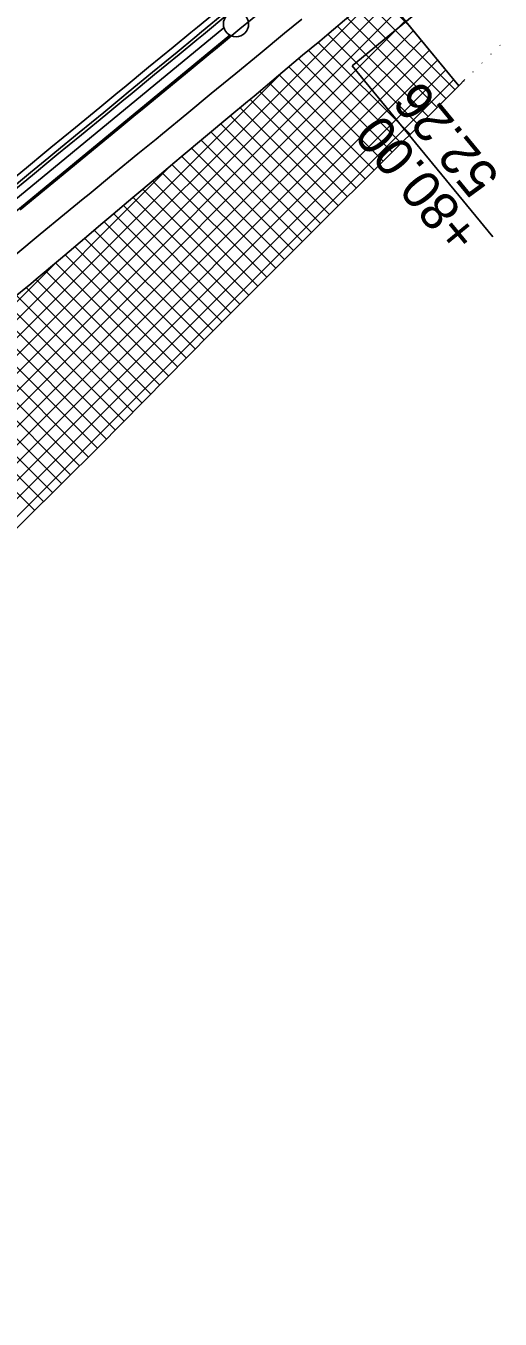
# Model space of a CAD drawing. Extents: x 1147550 to 1149124, y 2017436 to 2018779.
# Drawn here: x 1149049.5 to 1149124.5, y 2018399.2 to 2018603.7 of the extents above; entities that cross this region are included whole.
import ezdxf

# ---------------------------------------------------------------- set-up
doc = ezdxf.new("R2010")
doc.units = 0
for name, color, linetype in [('S_ELECTRIC_UTILITIES', 7, 'Continuous'), ('S_HEADWALL', 7, 'Continuous'), ('S_IRON_PIN_ANNOT', 7, 'Continuous'), ('S_MAILBOX', 7, 'Continuous'), ('S_SECONDARY_CTL', 7, 'Continuous'), ('S_TELEPHONE_UTILITIES', 7, 'Continuous'), ('S_TELEPHONE_UTILITIES_ANNOT', 7, 'Continuous')]:
    doc.layers.add(name, color=color, linetype=linetype)

msp = doc.modelspace()

# ---------------------------------------------------------------- linework, layer by layer
at = {"layer": 'S_ELECTRIC_UTILITIES'}
msp.add_lwpolyline([(1149101.12, 2018597.36), (1149123.36, 2018570.33)], dxfattribs=at)
at = {"layer": 'S_HEADWALL'}
msp.add_line((1149117.99, 2018594.17), (1149102.78, 2018612.66), dxfattribs=at)
at = {"layer": 'S_IRON_PIN_ANNOT'}
for p, q in [((1148922.38, 2018425.84), (1149105.68, 2018609.13)), ((1149104.93, 2018608.83), (1149110.52, 2018603.24)), ((1148923.66, 2018424.29), (1149106.95, 2018607.58)), ((1149101.87, 2018606.24), (1149115.95, 2018592.16)), ((1149103.4, 2018607.54), (1149117.37, 2018593.57)), ((1148924.94, 2018422.74), (1149108.23, 2018606.03)), ((1148926.21, 2018421.18), (1149109.51, 2018604.48)), ((1149100.34, 2018604.95), (1149114.52, 2018590.76)), ((1148927.49, 2018419.63), (1149110.78, 2018602.93)), ((1149097.27, 2018602.35), (1149111.69, 2018587.94)), ((1149098.8, 2018603.65), (1149113.1, 2018589.35)), ((1148928.77, 2018418.08), (1149112.06, 2018601.38)), ((1149095.74, 2018601.06), (1149110.27, 2018586.53)), ((1149124.46, 2018600.62), (1149124.49, 2018600.59)), ((1148931, 2018417.49), (1149113.34, 2018599.82)), ((1148944.72, 2018428.38), (1149114.61, 2018598.27)), ((1149092.65, 2018598.49), (1149107.43, 2018583.71)), ((1149094.19, 2018599.77), (1149108.85, 2018585.12)), ((1149123.04, 2018599.21), (1149123.07, 2018599.18)), ((1148921.11, 2018427.39), (1149089.87, 2018596.15)), ((1148963.77, 2018444.6), (1149115.89, 2018596.72)), ((1149091.11, 2018597.2), (1149106.02, 2018582.29)), ((1149120.19, 2018596.41), (1149120.22, 2018596.38)), ((1149121.61, 2018597.81), (1149121.64, 2018597.78)), ((1148996.51, 2018474.51), (1149117.17, 2018595.17)), ((1149088.04, 2018594.62), (1149103.18, 2018579.47)), ((1149089.57, 2018595.91), (1149104.6, 2018580.88)), ((1149118.76, 2018595), (1149118.8, 2018594.97)), ((1149084.97, 2018592.03), (1149100.35, 2018576.65)), ((1149086.5, 2018593.32), (1149101.76, 2018578.06)), ((1149083.43, 2018590.74), (1149098.93, 2018575.24)), ((1149080.34, 2018588.17), (1149096.09, 2018572.42)), ((1149081.88, 2018589.46), (1149097.51, 2018573.83)), ((1149078.8, 2018586.89), (1149094.68, 2018571)), ((1149075.71, 2018584.32), (1149091.85, 2018568.18)), ((1149077.25, 2018585.6), (1149093.27, 2018569.59)), ((1148919.83, 2018428.94), (1149072.62, 2018581.74)), ((1149072.63, 2018581.74), (1149089.02, 2018565.35)), ((1149074.17, 2018583.03), (1149090.44, 2018566.76)), ((1149071.09, 2018580.45), (1149087.61, 2018563.93)), ((1149068.03, 2018577.86), (1149084.78, 2018561.1)), ((1149069.56, 2018579.15), (1149086.2, 2018562.52)), ((1149066.49, 2018576.56), (1149083.37, 2018559.69)), ((1149063.42, 2018573.97), (1149080.54, 2018556.86)), ((1149064.96, 2018575.27), (1149081.95, 2018558.28)), ((1149061.89, 2018572.68), (1149079.12, 2018555.45)), ((1149058.82, 2018570.09), (1149076.32, 2018552.6)), ((1149060.36, 2018571.39), (1149077.72, 2018554.02)), ((1149055.76, 2018567.5), (1149073.51, 2018549.75)), ((1149057.29, 2018568.8), (1149074.91, 2018551.17)), ((1148918.55, 2018430.5), (1149054.51, 2018566.45)), ((1149054.22, 2018566.21), (1149072.11, 2018548.32)), ((1149051.14, 2018563.63), (1149069.3, 2018545.47)), ((1149052.68, 2018564.92), (1149070.7, 2018546.9)), ((1149049.6, 2018562.34), (1149067.9, 2018544.05)), ((1149046.51, 2018559.78), (1149065.09, 2018541.2)), ((1149048.05, 2018561.06), (1149066.49, 2018542.62)), ((1149043.41, 2018557.22), (1149062.29, 2018538.34)), ((1149044.96, 2018558.5), (1149063.69, 2018539.77)), ((1149041.87, 2018555.93), (1149060.88, 2018536.92)), ((1149038.78, 2018553.36), (1149058.03, 2018534.11)), ((1149040.33, 2018554.65), (1149059.45, 2018535.52)), ((1149037.24, 2018552.08), (1149056.61, 2018532.71)), ((1149034.15, 2018549.51), (1149053.76, 2018529.9)), ((1149035.7, 2018550.79), (1149055.18, 2018531.31)), ((1149031.07, 2018546.93), (1149050.91, 2018527.1)), ((1149032.61, 2018548.22), (1149052.33, 2018528.5))]:
    msp.add_line(p, q, dxfattribs=at)
for points in [[(1149118.94, 2018595.18), (1149117.96, 2018594.21), (1149105.52, 2018609.33)], [(1149100.94, 2018605.45), (1149097.12, 2018602.22), (1149095.99, 2018601.27), (1149093.28, 2018599.02), (1149089.45, 2018595.8), (1149085.62, 2018592.58), (1149084.56, 2018591.69), (1149081.79, 2018589.38), (1149077.95, 2018586.18), (1149074.1, 2018582.98), (1149073.1, 2018582.14), (1149070.28, 2018579.76), (1149066.46, 2018576.53), (1149062.64, 2018573.31), (1149061.71, 2018572.52), (1149058.81, 2018570.08), (1149054.99, 2018566.86), (1149051.16, 2018563.64), (1149050.3, 2018562.92), (1149047.32, 2018560.45)], [(1148725.05, 2018295.78), (1148737.29, 2018302.31), (1148759.39, 2018313.93), (1148781.46, 2018325.68), (1148803.37, 2018337.66), (1148825.28, 2018349.66), (1148846.98, 2018361.91), (1148869.23, 2018375.5), (1148890.45, 2018388.71), (1148911.17, 2018402.69), (1148932.43, 2018418.55), (1148951.91, 2018434.12), (1148970.58, 2018450.61), (1148989.32, 2018467.79), (1149007.56, 2018484.84), (1149025.52, 2018502.19), (1149043.36, 2018519.65), (1149061.14, 2018537.18), (1149078.8, 2018555.13), (1149096.46, 2018572.78), (1149114.15, 2018590.39), (1149117.96, 2018594.21)]]:
    msp.add_lwpolyline(points, dxfattribs=at)
at = {"layer": 'S_MAILBOX'}
msp.add_lwpolyline([(1149101.12, 2018597.36), (1149116.55, 2018610.09)], dxfattribs=at)
at = {"layer": 'S_SECONDARY_CTL'}
msp.add_lwpolyline([(1149047.32, 2018560.45), (1149050.3, 2018562.92), (1149051.16, 2018563.64), (1149054.99, 2018566.86), (1149058.81, 2018570.08), (1149061.71, 2018572.52), (1149062.64, 2018573.31), (1149066.46, 2018576.53), (1149070.28, 2018579.76), (1149073.1, 2018582.14), (1149074.1, 2018582.98), (1149077.95, 2018586.18), (1149081.79, 2018589.38), (1149084.56, 2018591.69), (1149085.62, 2018592.58), (1149089.45, 2018595.8), (1149093.28, 2018599.02), (1149095.99, 2018601.27), (1149097.12, 2018602.22), (1149100.94, 2018605.45)], dxfattribs=at)
at = {"layer": 'S_TELEPHONE_UTILITIES'}
for points in [[(1149045.77, 2018578.06), (1149049.63, 2018581.24), (1149052.56, 2018583.65), (1149053.49, 2018584.42), (1149057.36, 2018587.59), (1149061.22, 2018590.77), (1149064.07, 2018593.12), (1149065.08, 2018593.95), (1149068.94, 2018597.12), (1149072.8, 2018600.3), (1149075.59, 2018602.6), (1149076.66, 2018603.48), (1149080.52, 2018606.65)], [(1149048.63, 2018574.59), (1149052.49, 2018577.77), (1149055.42, 2018580.17), (1149056.35, 2018580.94), (1149060.22, 2018584.12), (1149064.08, 2018587.3), (1149066.93, 2018589.64), (1149067.94, 2018590.47), (1149071.8, 2018593.65), (1149075.66, 2018596.83), (1149078.45, 2018599.12), (1149079.52, 2018600), (1149083.38, 2018603.18), (1149087.24, 2018606.36)], [(1149046.41, 2018577.29), (1149050.27, 2018580.47), (1149053.19, 2018582.87), (1149054.13, 2018583.65), (1149057.99, 2018586.82), (1149061.85, 2018590), (1149064.71, 2018592.35), (1149065.71, 2018593.18), (1149069.57, 2018596.35), (1149073.44, 2018599.53), (1149076.23, 2018601.82), (1149077.3, 2018602.71), (1149081.16, 2018605.88)], [(1149046.73, 2018576.91), (1149050.59, 2018580.08), (1149053.51, 2018582.49), (1149054.45, 2018583.26), (1149058.31, 2018586.44), (1149062.17, 2018589.61), (1149065.02, 2018591.96), (1149066.03, 2018592.79), (1149069.89, 2018595.97), (1149073.75, 2018599.14), (1149076.54, 2018601.44), (1149077.61, 2018602.32), (1149081.48, 2018605.5)], [(1149047.95, 2018567.55), (1149051.81, 2018570.73), (1149055.67, 2018573.9), (1149058.59, 2018576.31), (1149059.53, 2018577.08), (1149063.39, 2018580.26), (1149067.25, 2018583.43), (1149070.11, 2018585.78), (1149071.11, 2018586.61), (1149074.98, 2018589.79), (1149078.84, 2018592.97), (1149081.63, 2018595.26), (1149082.7, 2018596.14), (1149086.56, 2018599.32), (1149090.42, 2018602.5), (1149093.14, 2018604.73)]]:
    msp.add_lwpolyline(points, dxfattribs=at)
at = {"layer": 'S_TELEPHONE_UTILITIES_ANNOT'}
for p, q in [((1148863.62, 2018424.64), (1149080.84, 2018603.35)), ((1148863.62, 2018424.64), (1149080.84, 2018603.35)), ((1148864.57, 2018423.48), (1149081.79, 2018602.19)), ((1148864.57, 2018423.48), (1149081.79, 2018602.19))]:
    msp.add_line(p, q, dxfattribs=at)
msp.add_circle((1149082.75, 2018603.95), 2, dxfattribs=at)

# ---------------------------------------------------------------- texts
at = {"layer": 'S_ELECTRIC_UTILITIES'}
for s, p in [('52.26', (1149124.62, 2018579.82)), ('+80.00', (1149121.57, 2018570.93))]:
    msp.add_text(s, height=6, rotation=129.4453, dxfattribs=at).set_placement(p)

doc.saveas('drawing.dxf')
